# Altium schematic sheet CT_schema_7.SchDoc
size 372 x 335 mm
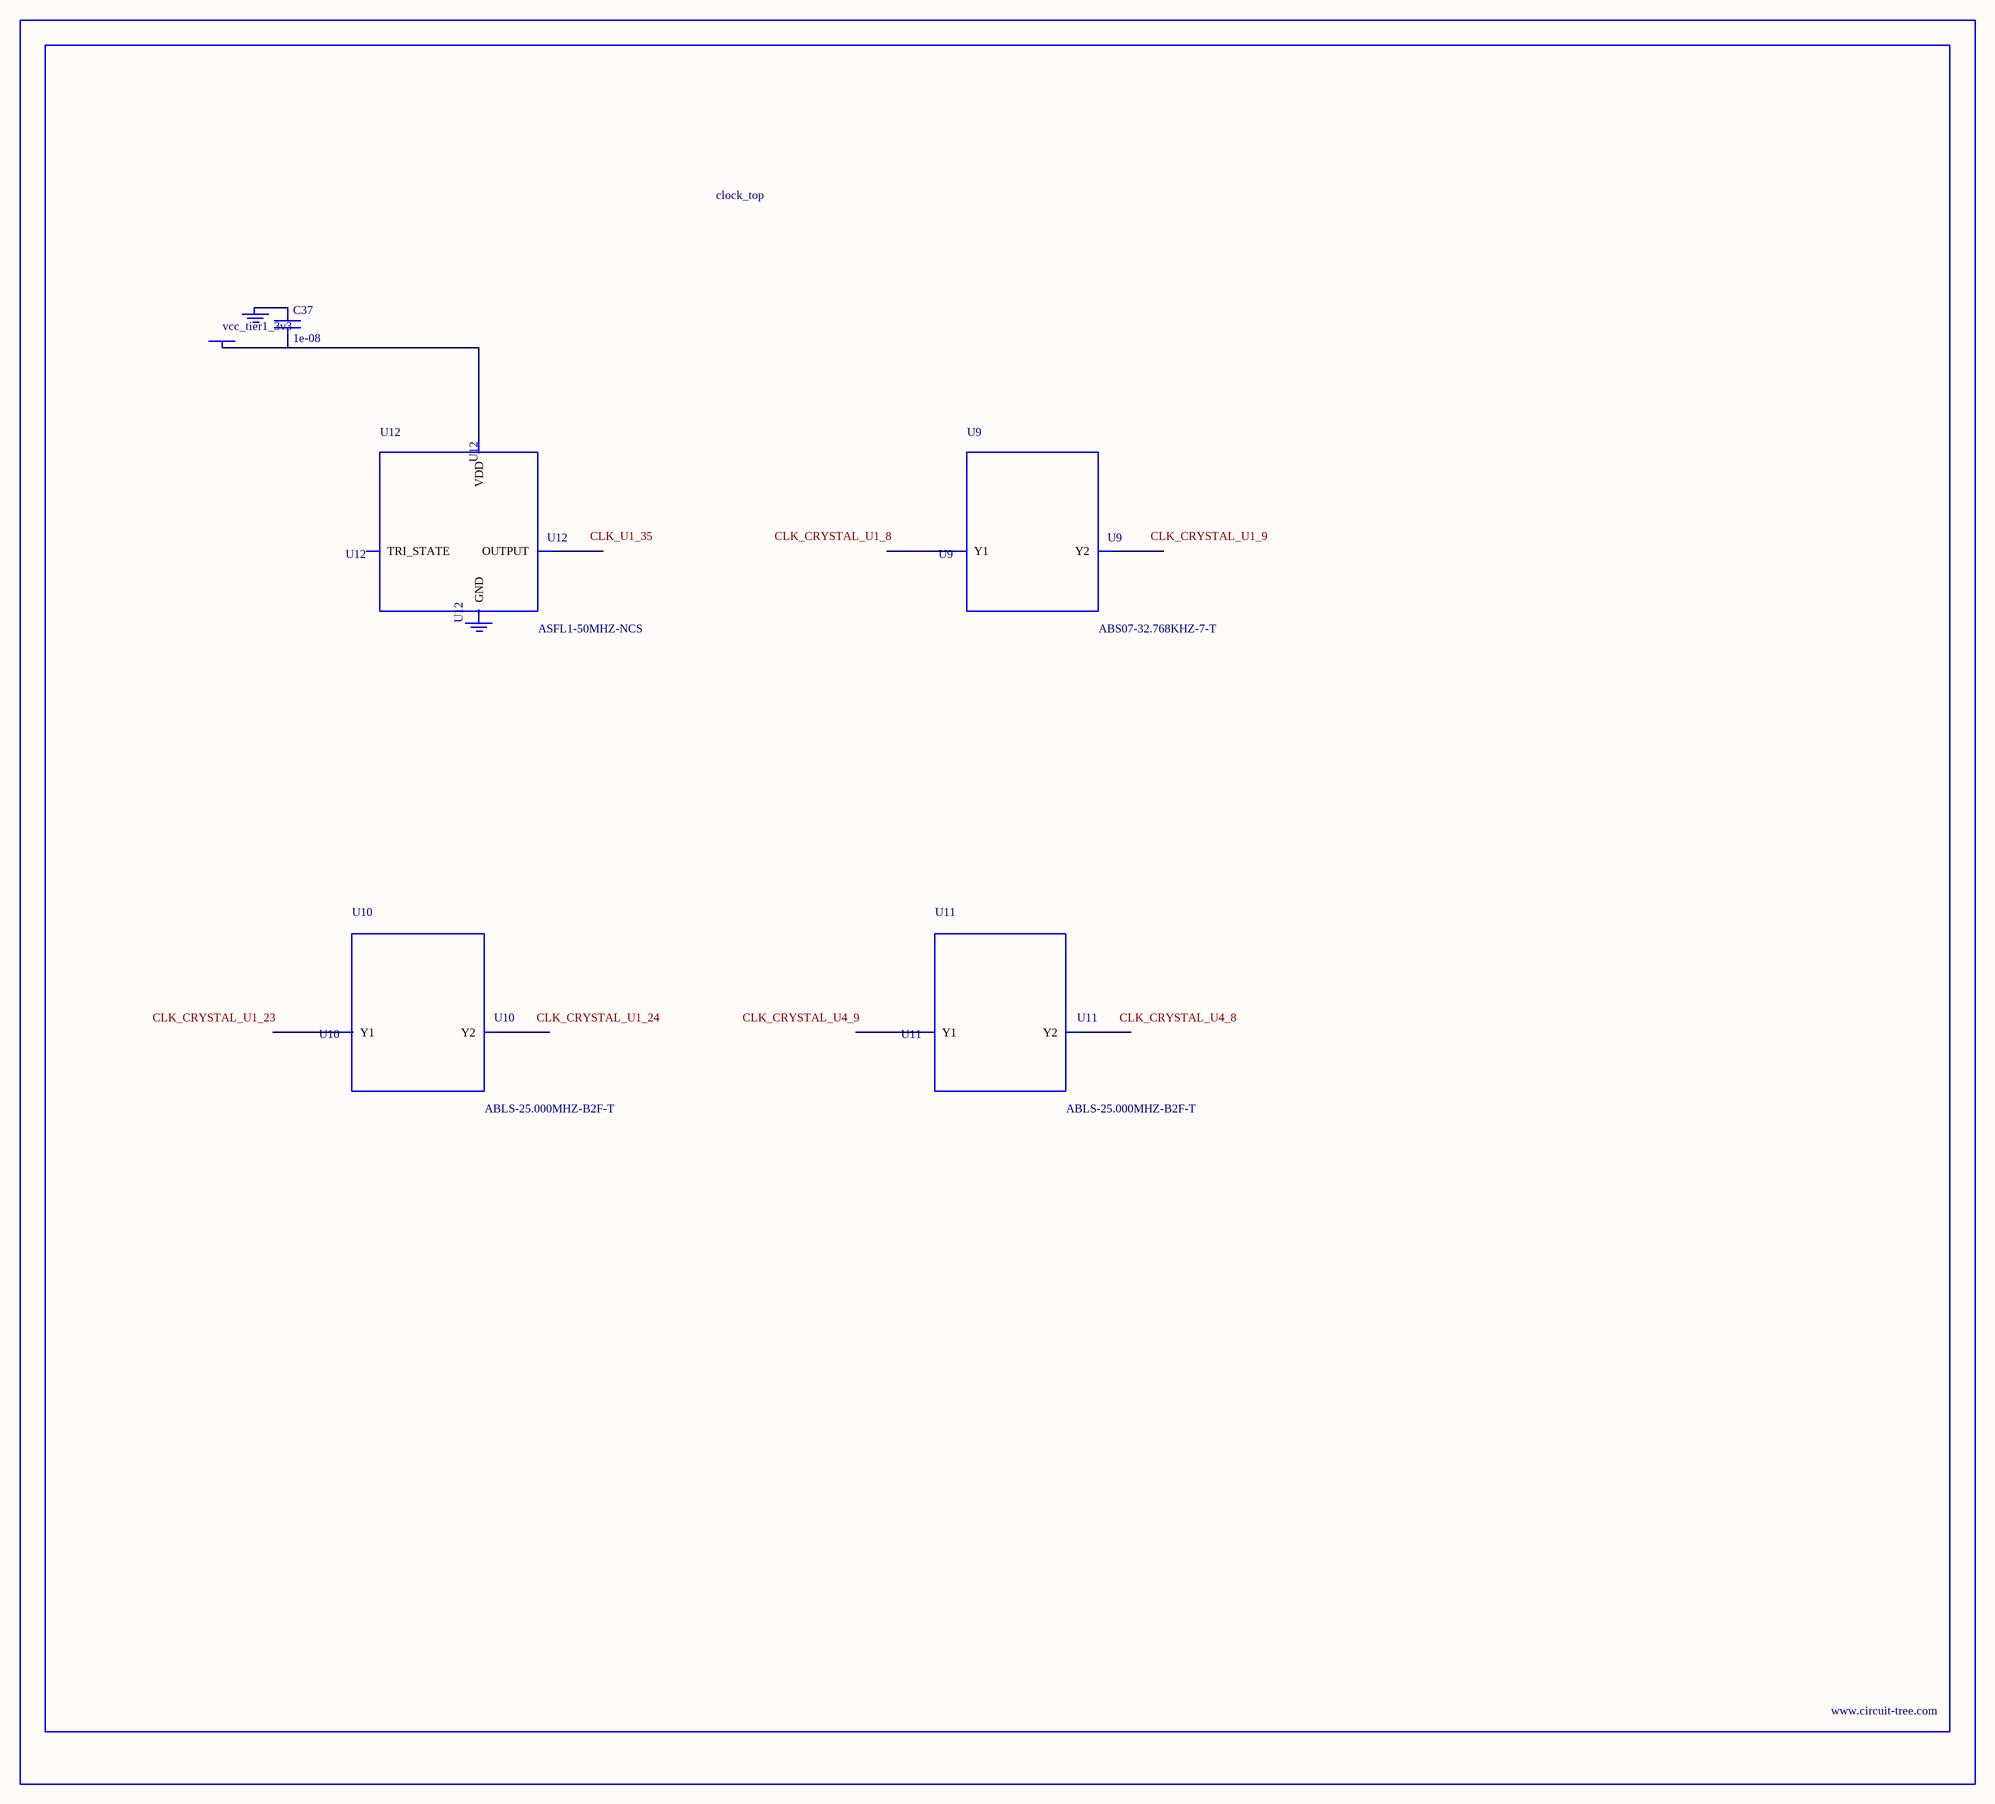
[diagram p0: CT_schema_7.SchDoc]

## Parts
BORDER6  (no value)
C37  1e-08  [C0402]
GND_INSTANCE_6_0  (no value)
GND_INSTANCE_6_1  (no value)
POWER_INSTANCE_6_0  vcc_tier1_3v3
U9  ABS07-32.768KHZ-7-T  [ABS07-32.768KHZ-7-T]
U10  ABLS-25.000MHZ-B2F-T  [ABLS-25.000MHZ-B2F-T]
U11  ABLS-25.000MHZ-B2F-T  [ABLS-25.000MHZ-B2F-T]
U12  ASFL1-50MHZ-NCS  [ASFL1]

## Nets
NetC37_1: C37.1 GND_INSTANCE_6_0.0(GND)
NetC37_2: C37.2 POWER_INSTANCE_6_0.0(PWR) U12.4(VDD)

Not connected (* = marked no-connect by the designer): GND_INSTANCE_6_1 0(GND); U9 1(Y1) 2(Y2); U10 1(Y1) 2(Y2); U11 1(Y1) 2(Y2); U12 1(TRI_STATE) 2(GND) 3(OUTPUT)

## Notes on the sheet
- Labels drawn without touching a wire or pin: CLK_CRYSTAL_U1_8, CLK_CRYSTAL_U1_9, CLK_CRYSTAL_U1_23, CLK_CRYSTAL_U1_24, CLK_CRYSTAL_U4_8, CLK_CRYSTAL_U4_9, CLK_U1_35

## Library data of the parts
BORDER6 = BORDER_PAGE6
C37 = C0402C103K3RAC
GND_INSTANCE_6_0 GND_INSTANCE_6_1 = GND
POWER_INSTANCE_6_0 = PWR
